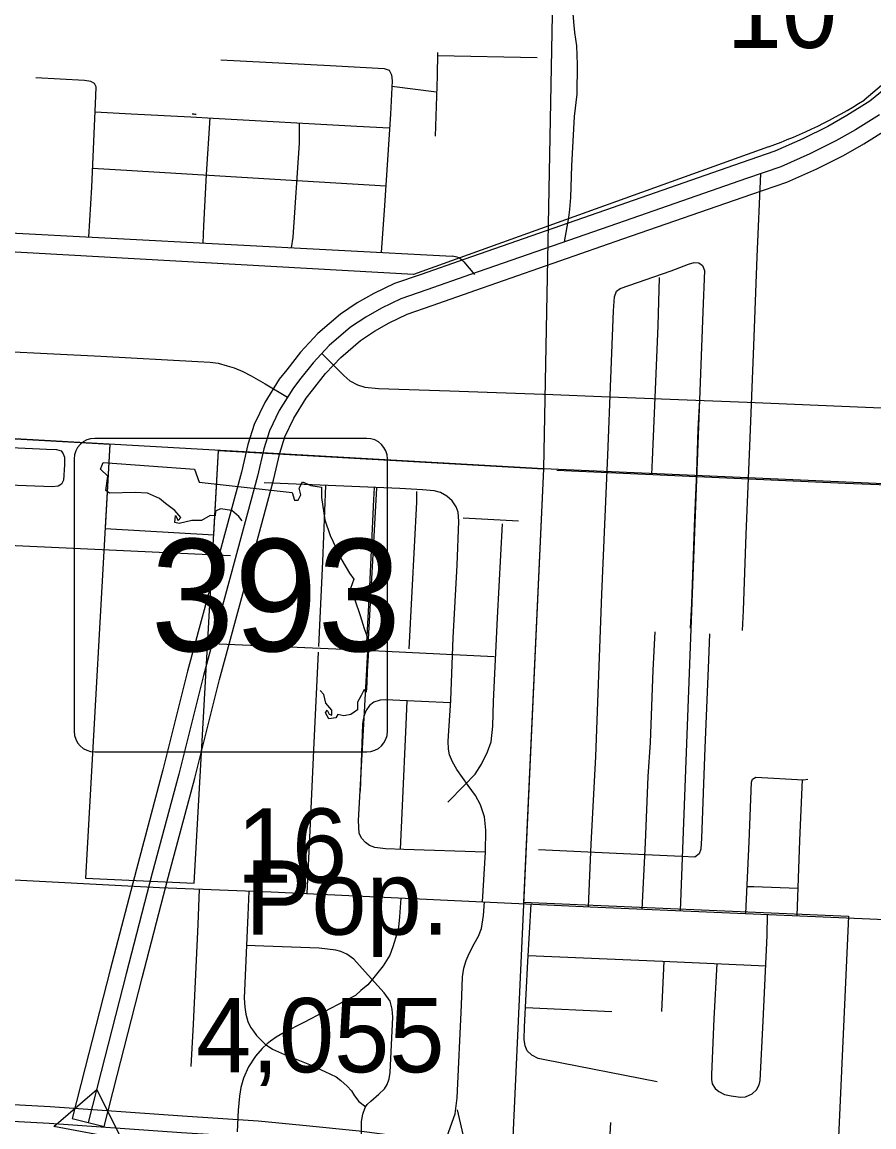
# Model space of a CAD drawing. Extents: x 1219626 to 1426462, y 456797 to 752399.
# Drawn here: x 1288589 to 1293754, y 518983 to 525679 of the extents above; entities that cross this region are included whole.
import ezdxf

# ---------------------------------------------------------------- set-up
doc = ezdxf.new("R2010")
doc.units = 0
for name, color, linetype in [('Cities Incorporated Area', 7, 'Continuous'), ('City Streets', 7, 'Continuous'), ('Local Roads Paved', 7, 'Continuous'), ('Masks', 7, 'Continuous'), ('Populations', 7, 'Continuous'), ('Roadshilelds State Highways', 7, 'Continuous'), ('Section Lines', 7, 'Continuous'), ('Section Numbers', 7, 'Continuous'), ('State Route Divided Highway Outline and Fill', 7, 'Continuous'), ('State Routes Highway Center Lines', 7, 'Continuous'), ('US Route Divided Highway Outline and Fill', 7, 'Continuous'), ('US Routes Highway Center Lines', 7, 'Continuous')]:
    doc.layers.add(name, color=color, linetype=linetype)

msp = doc.modelspace()

# ---------------------------------------------------------------- linework, layer by layer
at = {"layer": 'Cities Incorporated Area'}
for p, q in [((1294441.9, 525843.8), (1293695.8, 525206.3)), ((1293115.5, 524923.7), (1290963.1, 524150)), ((1290963.1, 524150), (1287578.9, 524340.3)), ((1286491.8, 523268.8), (1289121.5, 523120.6)), ((1286491.8, 523268.8), (1289121.5, 523120.6)), ((1289121.5, 523120.6), (1288973.3, 520491.1)), ((1289121.5, 523120.6), (1289092.7, 522609.4)), ((1289632.6, 520459.7), (1289780.5, 523083.5)), ((1289751.6, 522572.3), (1289780.5, 523083.5)), ((1289780.5, 523083.5), (1291751.2, 522972.4)), ((1289780.5, 523083.5), (1291751.2, 522972.4)), ((1291751.2, 522972.4), (1291629.8, 520345.1)), ((1291751.2, 522972.4), (1291629.8, 520345.1)), ((1289092.7, 522609.4), (1289751.6, 522572.3)), ((1288973.3, 520491.1), (1289632.6, 520459.7)), ((1291629.8, 520345.1), (1293599.1, 520260)), ((1291629.8, 520345.1), (1293599.1, 520260)), ((1293599.1, 520260), (1293515.2, 518366.3)), ((1293599.1, 520260), (1293515.2, 518366.3))]:
    msp.add_line(p, q, dxfattribs=at)
msp.add_arc((1292097.9, 527751), 3004.8, 289.7936, 302.126, dxfattribs=at)
at = {"layer": 'City Streets'}
for p, q in [((1291264.4, 522674), (1291599, 522656.6)), ((1292480.2, 519987), (1292465.7, 519682.2)), ((1292166, 519680.4), (1291640.6, 519704.6)), ((1292156.4, 519010.3), (1292136.3, 518609.6))]:
    msp.add_line(p, q, dxfattribs=at)
for points in [[(1292957.5, 521991.7), (1292963.6, 522113.1), (1292979.2, 522574.3), (1293001.7, 523109.2), (1293026, 523716.9), (1293046.8, 524256.1), (1293068, 524761.5)], [(1292024.5, 520316.8), (1292040.3, 520697.4), (1292067.1, 521227.9), (1292088.8, 521775.8), (1292105.3, 522211.9), (1292133, 522869), (1292140.8, 523054.6), (1292159, 523519.2), (1292174.6, 523928.4), (1292180.7, 524013.4), (1292192.8, 524048.9), (1292216.3, 524065.4), (1292524.9, 524172), (1292629.8, 524212.8), (1292663.6, 524221.5), (1292692.2, 524219.7), (1292715.6, 524204.1), (1292727.7, 524173.8), (1292716.5, 523924.1), (1292579.8, 520293.4)], [(1292452.9, 524132.2), (1292443.4, 523839.1), (1292425.2, 523403.9)], [(1285428.5, 523836), (1286358.4, 523789.1), (1287252.2, 523746.6), (1287706.5, 523722.3), (1288168.5, 523698.9), (1289066.7, 523655.6), (1289653.6, 523622.6), (1289729, 523618.3), (1289777.6, 523611.4), (1289833, 523596.6), (1289874.7, 523583.6), (1289928.4, 523561.9), (1289978.7, 523535.1), (1290061.9, 523486.5), (1290197.7, 523405.3)], [(1290406.3, 523670.7), (1290540.5, 523537.7), (1290576.9, 523505.6), (1290622.8, 523481.3), (1290667.9, 523466.6), (1290749.4, 523457.9), (1291182, 523444), (1291807.1, 523421.5), (1292102.7, 523411.1), (1292986.1, 523376.4), (1293846.1, 523340), (1294317.6, 523324.3)], [(1292425.2, 523403.9), (1292410.4, 523025.3), (1292404.9, 522937.3)], [(1292695.7, 523387.8), (1292687, 523212.3), (1292678.3, 522950.5), (1292667.1, 522677.4), (1292647.1, 522154.7), (1292639.3, 522005.6)], [(1288223.4, 522530.3), (1288238.1, 522865.8), (1288238.1, 522881.4), (1288202.6, 522883.1), (1288169.6, 522891.8), (1288148.8, 522914.3), (1288141.9, 522942.9), (1288150.5, 523079.9), (1288167, 523105.9), (1288193, 523115.5), (1288305.7, 523112), (1288736.6, 523091.2), (1288797.3, 523089.5), (1288825.9, 523080.8), (1288838.9, 523063.4), (1288845.8, 523042.6), (1288845.8, 522995.8), (1288840.6, 522903.9), (1288828.5, 522878.8), (1288806.8, 522867.5), (1288773, 522862.3), (1288239.8, 522882.3)], [(1291832.2, 522963.7), (1292546.6, 522930.8), (1293579.1, 522885.7), (1294349.8, 522854.5), (1295019.1, 522824.2), (1295494.1, 522806), (1296267.4, 522770.4), (1297025.2, 522736.6), (1298165.2, 522686.3), (1299007, 522649.1), (1299931.1, 522609.2), (1300557.8, 522581.7)], [(1291380.1, 520347.4), (1291398.7, 520647.9), (1291400.5, 520782.3), (1291393.5, 520862.1), (1291369.3, 520935.8), (1291338, 520991.3), (1291294.7, 521052.8), (1291225.3, 521149.9), (1291199.3, 521195), (1291181.1, 521237.5), (1291175.1, 521273), (1291173.3, 521321.6), (1291188.1, 521569.5), (1291201.9, 521946.6), (1291227.1, 522388.8), (1291237.5, 522654.9), (1291234, 522708.7), (1291221.9, 522741.6), (1291195.9, 522778), (1291163.8, 522806.6), (1291125.7, 522828.3), (1291087.5, 522837.8), (1291017.3, 522844.8), (1290880.3, 522851.7), (1290056.7, 522886.4)], [(1290428.2, 522870.7), (1290410.4, 522410.4), (1290387, 521895.5)], [(1291398.7, 520648.2), (1290902.8, 520665.3), (1290792.7, 520667.9), (1290727.7, 520676.6), (1290696.5, 520689.6), (1290670.5, 520707.8), (1290648.8, 520730.3), (1290633.2, 520762.4), (1290629.8, 520839.5), (1290631.5, 520875.1), (1290740.3, 522857.6)], [(1290724.8, 522858.2), (1290719.9, 522786.7), (1290694.8, 522259.6), (1290675.7, 521881.6)], [(1290935.8, 521879.9), (1290954, 522227.5), (1290983.5, 522770.2), (1290983.5, 522834.4)], [(1291169.9, 520952.2), (1291270.4, 521051.9), (1291336.3, 521121.3), (1291375.3, 521182), (1291411.7, 521256.5), (1291433.4, 521317.2), (1291442.9, 521412.6), (1291448.2, 521561.7), (1291471.6, 522068.9), (1291501.9, 522638.4)], [(1287527.2, 522554.6), (1288240.7, 522521.6), (1289248.1, 522473.9), (1289852.3, 522447.1)], [(1292756.4, 521971.8), (1292751.2, 521813.1), (1292728.6, 521281.7), (1292707.8, 520732.9), (1292704.3, 520666.2), (1292693.9, 520637.5), (1292668.8, 520617.6), (1292589, 520622.8), (1292191.1, 520641), (1291721.2, 520662.7)], [(1292349.5, 520303.1), (1292369.7, 520706), (1292386.2, 521106.6), (1292399.2, 521313.8), (1292416.5, 521752.4), (1292426.9, 521984.8)], [(1289783.6, 521911.9), (1290161.6, 521894.6), (1290586.4, 521876.4), (1291450.8, 521833.9)], [(1290317, 520397.2), (1290335, 520780.6), (1290360.1, 521311.2), (1290385.3, 521859.9)], [(1291187.1, 521553.1), (1291010.3, 521561.7), (1290792.7, 521571.2), (1290760.7, 521569.5), (1290721.7, 521557.4), (1290694.8, 521538.3), (1290673.1, 521505.3), (1290663.6, 521477.6), (1290656.6, 521451.6), (1290654, 521424.7), (1290639.3, 521017.3)], [(1290921.3, 521565.6), (1290916.7, 521423), (1290894.2, 520928.8), (1290881.3, 520665.8)], [(1292977.4, 520276.5), (1292997.4, 520710.4), (1293012.1, 521073.6), (1293018.2, 521091), (1293038.1, 521102.2), (1293326.8, 521087.5), (1293352.8, 521091)], [(1293319.6, 521087.9), (1293302.5, 520719.9), (1293286.4, 520263)], [(1285474.1, 520696.9), (1285590.3, 520679.6), (1285708.2, 520659.7), (1285862.5, 520619.8), (1285989.1, 520603.3), (1286157.2, 520584.2), (1286538.7, 520569.5), (1286778, 520568.6), (1287077.1, 520555.6), (1287444.6, 520540), (1288385.3, 520488.9), (1289423, 520434.2), (1290099.2, 520407.4), (1291339.8, 520349.3), (1292034.2, 520316.3), (1292880.3, 520280.8), (1293729.1, 520243.5), (1294688.8, 520201)], [(1289615, 519348.4), (1289628.9, 519605.9), (1289655.8, 520209.3), (1289665.2, 520424.6)], [(1293292.2, 520428), (1293025.1, 520438.1), (1292984.9, 520438.1)], [(1290886, 520370.5), (1290877.7, 520256.5), (1290870.8, 520194.1), (1290862.5, 520160.3), (1290837, 520074), (1290818.8, 520024.6), (1290778.9, 519960.5), (1290721.7, 519889.4), (1290686.1, 519845.2), (1290643.6, 519809.6), (1290610.7, 519780.1), (1290543.9, 519744.6), (1290297.7, 519616.3), (1290179, 519555.6), (1290129.5, 519527), (1290095.7, 519502.7), (1290074.9, 519486.3), (1290043.7, 519459.4), (1290003.8, 519411.7), (1289961.4, 519346.7), (1289931, 519278.2), (1289914.5, 519221.8), (1289906.7, 519169.8), (1289899.8, 519085.7), (1289893.7, 518954)], [(1289963.9, 520412.7), (1289957.5, 520267.4), (1289934.9, 519762.8), (1289939.2, 519708.2), (1289946.2, 519665.7), (1289958.3, 519622.4), (1289974.8, 519587.7), (1289991.3, 519564.3), (1290009.5, 519538.3), (1290063.2, 519485.4), (1290106.6, 519454.2), (1290180.3, 519423), (1290331.1, 519361.4), (1290425.6, 519319.8), (1290492.4, 519286), (1290521, 519265.2), (1290560, 519230.5), (1290586.8, 519201), (1290605.1, 519172.4), (1290631.1, 519137.7), (1290673.3, 519105.3)], [(1291118, 518791.9), (1291214.9, 519063.2), (1291227.1, 519159.4), (1291253.1, 519721.2), (1291260, 519892.8), (1291267, 519945.7), (1291281.7, 519991.7), (1291300.8, 520035), (1291330.2, 520092.2), (1291356.3, 520139.9), (1291374.5, 520185.9), (1291387.5, 520263.9), (1291393.3, 520346.7)], [(1292439.1, 519257.4), (1291758.5, 519389.2), (1291718.6, 519398.7), (1291679.6, 519418.6), (1291651.9, 519444.6), (1291638.9, 519474.1), (1291632.8, 519514), (1291634.5, 519590.3), (1291655.3, 519985.6), (1291675.5, 520333.4)], [(1292802, 519972.8), (1292784.1, 519638), (1292769.4, 519300.7), (1292769.4, 519270.4), (1292773.7, 519244.4), (1292791.9, 519215.8), (1292813.6, 519198.4), (1292847.4, 519179.4), (1292888.1, 519170.7), (1292944.5, 519162.9), (1292974.8, 519165.5), (1293016.4, 519183.7), (1293041.6, 519208), (1293058.1, 519237.4), (1293065, 519264.3), (1293082.3, 519623.2), (1293107.5, 520144.3), (1293109.5, 520270.7)], [(1290646.2, 518856.6), (1290647.5, 519016.4), (1290654.5, 519059.7), (1290670.1, 519100.5), (1290682.2, 519118.7), (1290703.9, 519139.5), (1290751.6, 519181.1), (1290786.2, 519214), (1290802.7, 519240), (1290815.7, 519274.7), (1290821.8, 519313.7), (1290836.5, 519647.5), (1290833.1, 519696.9), (1290821.8, 519746.3), (1290783.6, 519795.7), (1290670.1, 519922.3), (1290600.7, 519999.5), (1290557.4, 520029.8), (1290521.8, 520047.2), (1290490.6, 520055), (1290390.1, 520066.2), (1290054.6, 520078.4), (1289949.2, 520082.2)], [(1291657.5, 520022.8), (1292472.9, 519987.3), (1293098.6, 519959.8)], [(1291301.8, 518762.3), (1291278.2, 518875.9), (1291229.7, 519086.6)]]:
    msp.add_lwpolyline(points, dxfattribs=at)
at = {"layer": 'Local Roads Paved'}
for p, q in [((1291108.3, 525477.2), (1291711.8, 525463.8)), ((1290830.6, 525290.9), (1291102.1, 525257.3)), ((1287581.3, 524451.3), (1291197.5, 524260.4)), ((1291268.3, 524225.4), (1291332.6, 524150))]:
    msp.add_line(p, q, dxfattribs=at)
for points in [[(1290534.4, 527031.2), (1291248.9, 526936.5), (1291395.9, 526925.8), (1291473.2, 526909.4), (1291547.7, 526874.6), (1291596, 526822.4), (1291629.9, 526768.2), (1291686, 526627.1), (1291894.8, 526053.7), (1291909.3, 525999.5), (1291922.9, 525926.1), (1291926.7, 525821.6), (1291928.7, 525728.8), (1291934.5, 525659.2), (1291939.3, 525616.7), (1291949.9, 525536.4), (1291954.8, 525423.3), (1291952.8, 525242.5), (1291937.4, 525107.1), (1291920.9, 524808.3), (1291914.2, 524615.9), (1291907.4, 524544.4), (1291901.6, 524496), (1291875.6, 524346.8)], [(1289793.7, 525450.8), (1290458, 525416), (1290784.8, 525398.6), (1290814.8, 525387), (1290828.3, 525359), (1290832.2, 525324.2), (1290822.5, 525121.1), (1290785.8, 524567.1), (1290765.5, 524283.2)], [(1291108.7, 525494.8), (1291104.9, 525350.8), (1291094.2, 524988.2)], [(1288993.5, 524376.8), (1289011.5, 524678.3), (1289035.7, 525233.3), (1289037.6, 525286.5), (1289028.9, 525307.7), (1289004.8, 525319.3), (1288968, 525325.1), (1288671.2, 525342.5)], [(1289031.4, 525135.5), (1289251.3, 525124), (1289612, 525105.6), (1289747.3, 525096.9), (1290618.5, 525049.6), (1290817.1, 525039)], [(1289687, 524340.1), (1289690.3, 524444.3), (1289707.7, 524754.7), (1289728.8, 525098.1)], [(1290269.5, 525068.6), (1290269.5, 524946.1), (1290229.8, 524375.6), (1290221.4, 524311.9)], [(1290793.6, 524684.5), (1290188.2, 524721.8), (1289222.3, 524780.8), (1289016.5, 524792)]]:
    msp.add_lwpolyline(points, dxfattribs=at)
for centre, radius, start, end in [((1295641.6, 526755.2), 1900, 178.55051, 220.51633), ((1289581, 524322), 800, 85.38705, 87.25054), ((1291192.2, 524160.5), 100, 40.41973, 86.97756)]:
    msp.add_arc(centre, radius, start, end, dxfattribs=at)
at = {"layer": 'Masks'}
msp.add_lwpolyline([(1288781.9, 518986.6), (1289042.5, 519209.8), (1289191.5, 518908.1)], close=True, dxfattribs=at)
at = {"layer": 'Roadshilelds State Highways'}
for p, q in [((1290679.2, 523156.4), (1289029.2, 523156.4)), ((1288904.2, 523031.4), (1288904.2, 521381.4)), ((1290804.2, 521381.4), (1290804.2, 523031.4)), ((1289029.2, 521256.4), (1290679.2, 521256.4))]:
    msp.add_line(p, q, dxfattribs=at)
for points in [[(1289923.8, 522657.3), (1289904.1, 522682.7), (1289861.3, 522718.9), (1289792, 522728.8), (1289762.4, 522715.6), (1289759.1, 522686), (1289729.4, 522689.3), (1289676.7, 522659.6), (1289617.3, 522659.6), (1289541.5, 522639.8), (1289515.1, 522646.4), (1289518.4, 522689.3), (1289534.9, 522659.6), (1289551.4, 522676.1), (1289515.1, 522718.9), (1289459.1, 522761.8), (1289422.8, 522791.5), (1289350.3, 522824.5), (1289274.5, 522827.8), (1289119.6, 522824.5), (1289096.5, 522841), (1289109.7, 522926.7), (1289063.5, 522969.6), (1289080, 523009.2)], [(1289080, 523009.2), (1289633.8, 522969.6), (1289663.5, 522890.5), (1290227.2, 522827.8), (1290240.4, 522781.6), (1290263.4, 522781.6), (1290279.9, 522814.6), (1290270, 522854.2), (1290289.8, 522893.8), (1290339.3, 522870.7), (1290405.2, 522860.8), (1290405.2, 522798.1), (1290425, 522662.9), (1290457.9, 522567.2), (1290527.2, 522418.8), (1290573.3, 522339.6), (1290599.7, 522303.4), (1290579.9, 522247.3), (1290606.3, 522178), (1290639.2, 522082.4), (1290662.3, 522003.2), (1290688.7, 521934), (1290688.7, 521871.3), (1290682.1, 521746), (1290678.8, 521673.4), (1290675.5, 521617.3), (1290662.3, 521633.8), (1290645.8, 521597.5), (1290622.8, 521557.9), (1290622.8, 521511.8), (1290583.2, 521482.1), (1290540.3, 521475.5), (1290504.1, 521482.1), (1290490.9, 521462.3), (1290448, 521455.7), (1290428.3, 521492), (1290438.2, 521508.5), (1290451.3, 521485.4), (1290467.8, 521478.8), (1290467.8, 521508.5), (1290431.6, 521551.4), (1290418.4, 521604.1), (1290395.9, 521628.7)]]:
    msp.add_lwpolyline(points, dxfattribs=at)
for centre, start, end in [((1289029.2, 523031.4), 90, 180), ((1290679.2, 523031.4), 0, 90), ((1289029.2, 521381.4), 180, 270), ((1290679.2, 521381.4), 270, 0)]:
    msp.add_arc(centre, 125, start, end, dxfattribs=at)
at = {"layer": 'Section Lines'}
for p, q in [((1291851.8, 528305.1), (1291751.2, 522972.4)), ((1291751.2, 522972.4), (1286491.8, 523268.8)), ((1291751.2, 522972.4), (1291519.9, 517967.5)), ((1296995.2, 522740.1), (1291751.2, 522972.4))]:
    msp.add_line(p, q, dxfattribs=at)
at = {"layer": 'State Route Divided Highway Outline and Fill'}
msp.add_line((1288893.5, 519035.2), (1289087.3, 518985.8), dxfattribs=at)
for points in [[(1293925, 525359.3), (1293728.9, 525199.6), (1293590.4, 525112.8), (1293475.1, 525047.2), (1293323.5, 524971), (1293153.3, 524896.1), (1292948.4, 524826.6), (1292166.1, 524553.8), (1291274.3, 524243.3), (1291009.8, 524150.3), (1290847.3, 524095.1), (1290722.2, 524034.6), (1290621.3, 523977), (1290519.1, 523909.6), (1290382.1, 523791.3), (1290277.6, 523679.4), (1290193.3, 523572.1), (1290148.4, 523514.7), (1290060, 523374.3), (1289996.3, 523239.5), (1289958.1, 523118.6), (1289919.8, 522951.6), (1289758.3, 522354.9), (1289592.2, 521744.7), (1289442.7, 521146.8), (1289281.8, 520545.7), (1289123.5, 519935.8), (1288972.1, 519343.7), (1288893.5, 519035.2)], [(1289087.3, 518985.8), (1289165.8, 519294.3), (1289317.1, 519885.9), (1289475.2, 520494.7), (1289636.3, 521096.7), (1289785.7, 521694.1), (1289951.4, 522302.5), (1290113.9, 522903.1), (1290151.3, 523066), (1290183, 523166.3), (1290235.7, 523277.9), (1290312.2, 523399.5), (1290350.8, 523448.8), (1290429.5, 523549.1), (1290520.9, 523646.9), (1290640.1, 523749.8), (1290726.1, 523806.5), (1290815.4, 523857.6), (1290923.2, 523909.7), (1291075.1, 523961.2), (1291340.3, 524054.5), (1292231.9, 524364.9), (1293013.5, 524637.4), (1293225.8, 524709.5), (1293408.8, 524790), (1293569.6, 524870.9), (1293693, 524941.1), (1293845.6, 525036.7)]]:
    msp.add_lwpolyline(points, dxfattribs=at)
at = {"layer": 'State Routes Highway Center Lines'}
msp.add_lwpolyline([(1293787.2, 525118.2), (1293641.7, 525027), (1293522.4, 524959), (1293366.2, 524880.5), (1293189.6, 524802.8), (1292981, 524732), (1292199, 524459.4), (1291307.3, 524148.9), (1291042.4, 524055.7), (1290885.2, 524002.4), (1290768.8, 523946.1), (1290673.7, 523891.8), (1290579.6, 523829.7), (1290451.5, 523719.1), (1290353.5, 523614.3), (1290272, 523510.5), (1290230.3, 523457.1), (1290147.9, 523326.1), (1290089.6, 523202.9), (1290054.7, 523092.3), (1290016.9, 522927.3), (1289854.8, 522328.7), (1289688.9, 521719.4), (1289539.5, 521121.7), (1289378.5, 520520.2), (1289220.3, 519910.9), (1289068.9, 519319), (1288990.4, 519010.5)], dxfattribs=at)
at = {"layer": 'US Route Divided Highway Outline and Fill'}
msp.add_lwpolyline([(1280888.2, 519565.9), (1281662, 519520.3), (1282801.1, 519446.4), (1283959.5, 519380.2), (1285265, 519304.1), (1286389.9, 519236.7), (1287562.5, 519171.5), (1288760, 519106.2), (1289561.5, 519049.7), (1290020.5, 519020.2), (1290290.8, 518994), (1290633.7, 518959), (1290972, 518915.2), (1291246, 518873.6), (1291813.2, 518774.3), (1292429.2, 518654.6), (1293480.7, 518452.3), (1294608.9, 518225.2)], dxfattribs=at)
at = {"layer": 'US Routes Highway Center Lines'}
msp.add_lwpolyline([(1280879.8, 519466.2), (1281655.8, 519420.5), (1282795, 519346.6), (1283953.7, 519280.3), (1285259.1, 519204.2), (1286384.1, 519136.8), (1287557, 519071.6), (1288753.7, 519006.4), (1289554.8, 518949.9), (1290012.4, 518920.5), (1290280.9, 518894.4), (1290622.2, 518859.7), (1290958.1, 518816.2), (1291229.8, 518774.9), (1291795, 518676), (1292410.3, 518556.4), (1293461.4, 518354.2), (1294589.6, 518127)], dxfattribs=at)

# ---------------------------------------------------------------- texts
at = {"layer": 'Populations'}
for s, p in [('Pop.', (1289942.1, 520148.2)), ('4,055', (1289644.4, 519314.3))]:
    msp.add_text(s, height=450, dxfattribs=at).set_placement(p)
at = {"layer": 'Roadshilelds State Highways'}
msp.add_text('393', height=680, dxfattribs=at).set_placement((1289369.1, 521866.4))
at = {"layer": 'Section Numbers'}
for s, rotation, p in [('10', 0.00034, (1292862.2, 525522.8)), ('16', 0.00035, (1289890.8, 520463.4))]:
    msp.add_text(s, height=450, rotation=rotation, dxfattribs=at).set_placement(p)

doc.saveas('drawing.dxf')
